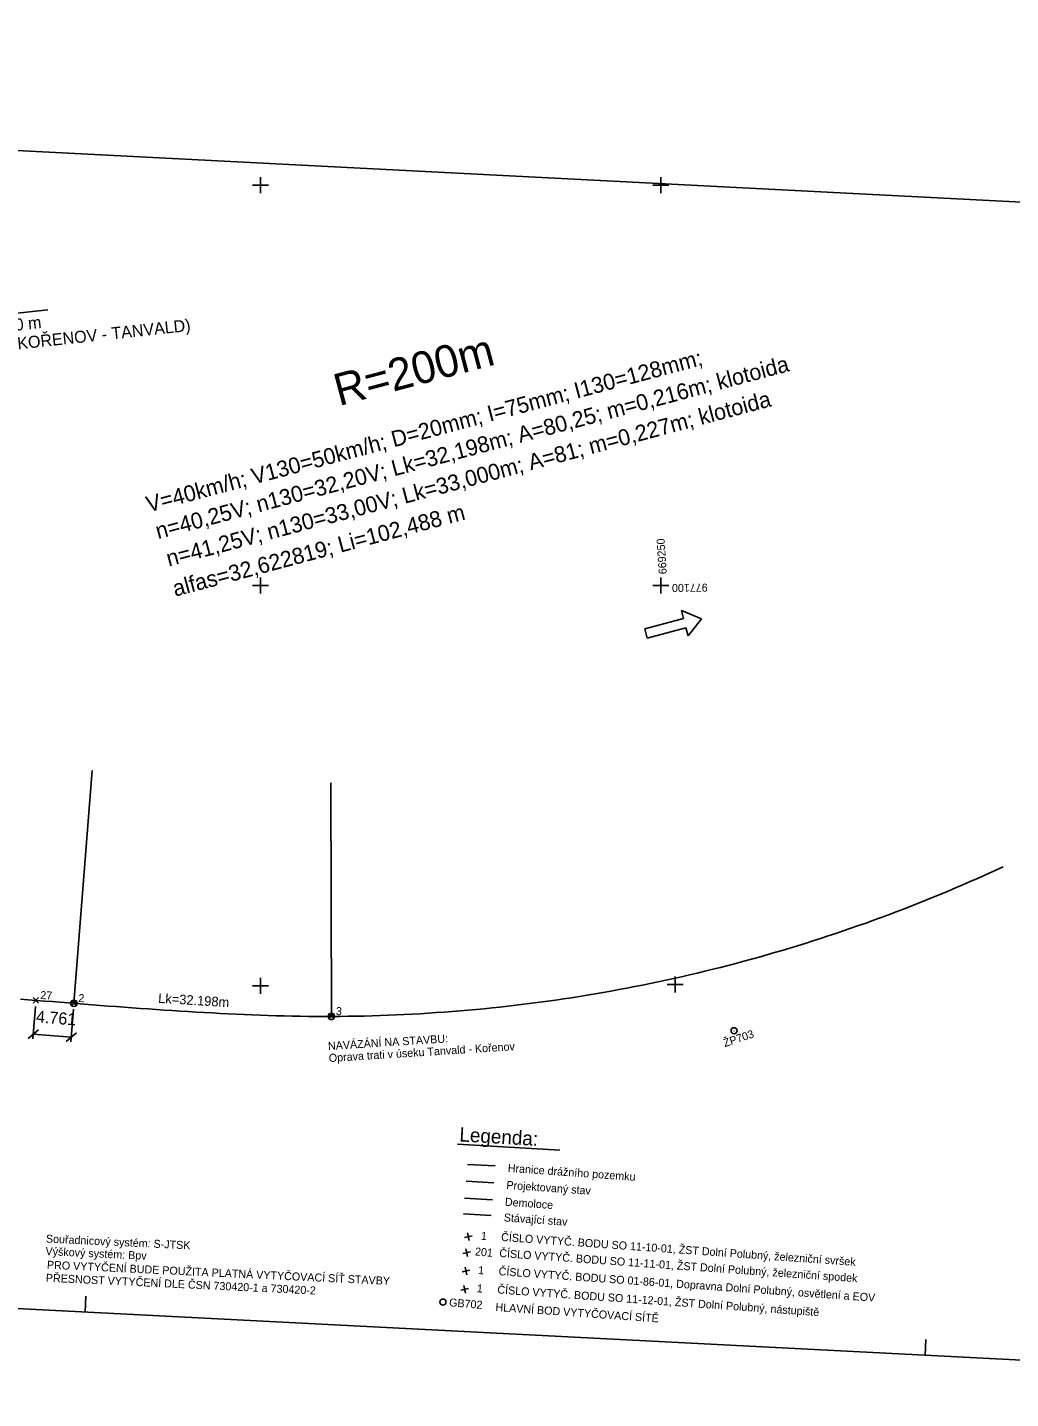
# Model space of a CAD drawing. Extents: x -669661 to -669105, y -977202 to -977030.
# Drawn here: x -669329.1 to -669206.3, y -977201.6 to -977030.3 of the extents above; entities that cross this region are included whole.
import ezdxf

# ---------------------------------------------------------------- set-up
doc = ezdxf.new("R2010")
doc.units = 0
for name, color, linetype in [('000_rozpiska', 7, 'Continuous'), ('_osa popis', 7, 'Continuous'), ('_sklonovníky', 7, 'Continuous'), ('Katastr_HRANICE DRÁHY', 7, 'Continuous'), ('KOL_lomy sklonů', 7, 'Continuous'), ('legenda', 7, 'Continuous'), ('legenda barvy', 7, 'Continuous'), ('legenda_text', 7, 'Continuous'), ('OST_smery', 7, 'Continuous'), ('POP_koleje_hlavní', 7, 'Continuous'), ('POP_koleje_oblouky', 7, 'Continuous'), ('POP_koleje_popis směrové hlavní body a parametry oblouků', 7, 'Continuous'), ('POP_kóty', 7, 'Continuous'), ('POP_sovisející_stavba', 7, 'Continuous'), ('PROGI_rozpiska', 7, 'Continuous'), ('SO 01-20-01_Demolice', 7, 'Continuous'), ('SO 01-86-01_vytyč_body', 7, 'Continuous'), ('SO 11-10-01_vytyč_body', 7, 'Continuous'), ('SO 11-11-01_vytyč_body', 7, 'Continuous'), ('SO 11-12-01_vytyč_body', 7, 'Continuous'), ('Stávající stav', 7, 'Continuous'), ('Vrstva 63', 7, 'Continuous'), ('čtvercová síť', 7, 'Continuous'), ('ŽBP', 7, 'Continuous')]:
    doc.layers.add(name, color=color, linetype=linetype)

# ---------------------------------------------------------------- blocks, each defined once
blk = doc.blocks.new('_Oblique')
blk.add_line((-0.5, -0.5), (0.5, 0.5))
blk = doc.blocks.new('POINT_DISPLAY')
for p, q in [((-0.35, -0.35), (0.35, 0.35)), ((-0.35, 0.35), (0.35, -0.35))]:
    blk.add_line(p, q)

msp = doc.modelspace()

# ---------------------------------------------------------------- linework, layer by layer
at = {"layer": '000_rozpiska'}
for p, q in [((-669321.79, -977188.79), (-669321.89, -977190.79)), ((-669216.93, -977194.19), (-669217.03, -977196.18))]:
    msp.add_line(p, q, dxfattribs=at)
at = {"layer": 'Defpoints'}
for p, q in [((-669629.05, -977030.28), (-669104.74, -977057.27)), ((-669629.05, -977030.28), (-669104.74, -977057.27)), ((-669636.48, -977174.59), (-669112.17, -977201.58)), ((-669636.48, -977174.59), (-669112.17, -977201.58))]:
    msp.add_line(p, q, dxfattribs=at)
at = {"layer": 'Katastr_HRANICE DRÁHY'}
msp.add_line((-669270.69, -977172.52), (-669274.16, -977172.32), dxfattribs=at)
at = {"layer": 'KOL_lomy sklonů'}
msp.add_lwpolyline([(-669341.46, -977067.18), (-669326.55, -977065.58)], dxfattribs=at)
at = {"layer": 'legenda barvy'}
msp.add_line((-669270.85, -977174.64), (-669274.33, -977174.43), dxfattribs=at)
at = {"layer": 'legenda_text'}
msp.add_line((-669275.39, -977169.8), (-669262.61, -977170.55), dxfattribs=at)
at = {"layer": 'OST_smery'}
for p, q in [((-669247.45, -977103.11), (-669244.94, -977104.16)), ((-669247.45, -977103.11), (-669247.18, -977104.13)), ((-669252.02, -977105.4), (-669247.18, -977104.13)), ((-669246.61, -977106.31), (-669244.94, -977104.16)), ((-669252.02, -977105.4), (-669251.71, -977106.57)), ((-669251.71, -977106.57), (-669246.88, -977105.29)), ((-669246.88, -977105.29), (-669246.61, -977106.31))]:
    msp.add_line(p, q, dxfattribs=at)
at = {"layer": 'POP_koleje_hlavní'}
for centre in [(-669323.3, -977152.2), (-669291.15, -977153.84)]:
    msp.add_circle(centre, 0.4, dxfattribs=at)
at = {"layer": 'POP_koleje_popis směrové hlavní body a parametry oblouků'}
for points in [[(-669321.01, -977123.12), (-669323.3, -977152.2)], [(-669291.22, -977124.66), (-669291.15, -977153.84)]]:
    msp.add_lwpolyline(points, dxfattribs=at)
at = {"layer": 'POP_kóty'}
for p, q in [((-669328.1, -977152.58), (-669328.42, -977156.66)), ((-669323.36, -977152.95), (-669323.68, -977157.03)), ((-669328.38, -977156.06), (-669323.63, -977156.43))]:
    msp.add_line(p, q, dxfattribs=at)
at = {"layer": 'POP_sovisející_stavba'}
for points in [[(-669290.76, -977153.84), (-669290.05, -977153.83), (-669289.05, -977153.82), (-669288.05, -977153.81), (-669287.05, -977153.79), (-669286.05, -977153.76), (-669285.06, -977153.73), (-669284.06, -977153.69), (-669283.06, -977153.65), (-669282.06, -977153.61), (-669281.06, -977153.56), (-669280.06, -977153.5), (-669279.06, -977153.44), (-669278.06, -977153.37), (-669277.07, -977153.3), (-669276.07, -977153.23), (-669275.07, -977153.15), (-669274.08, -977153.06), (-669273.08, -977152.97), (-669272.09, -977152.88), (-669271.09, -977152.77), (-669270.1, -977152.67), (-669269.1, -977152.56), (-669268.11, -977152.44), (-669267.12, -977152.32), (-669266.12, -977152.2), (-669265.13, -977152.07), (-669264.14, -977151.93), (-669263.15, -977151.79), (-669262.16, -977151.65), (-669261.17, -977151.5), (-669260.19, -977151.34), (-669259.2, -977151.18), (-669258.21, -977151.01), (-669257.23, -977150.84), (-669256.24, -977150.67), (-669255.26, -977150.49), (-669254.28, -977150.31), (-669253.29, -977150.12), (-669252.31, -977149.92), (-669251.33, -977149.72), (-669250.35, -977149.52), (-669249.38, -977149.31), (-669248.4, -977149.09), (-669247.42, -977148.88), (-669246.45, -977148.65), (-669245.48, -977148.42), (-669244.5, -977148.19), (-669243.53, -977147.95), (-669242.56, -977147.71), (-669241.59, -977147.46), (-669240.63, -977147.21), (-669239.66, -977146.95), (-669238.7, -977146.69), (-669237.73, -977146.42), (-669236.77, -977146.15), (-669235.81, -977145.87), (-669234.85, -977145.59), (-669233.89, -977145.3), (-669232.93, -977145.01), (-669231.98, -977144.71), (-669231.03, -977144.41), (-669230.07, -977144.1), (-669229.12, -977143.79), (-669228.17, -977143.48), (-669227.23, -977143.16), (-669226.28, -977142.83), (-669225.34, -977142.5), (-669224.39, -977142.17), (-669223.45, -977141.83), (-669222.51, -977141.49), (-669221.58, -977141.14), (-669220.64, -977140.79), (-669219.71, -977140.43), (-669218.78, -977140.07), (-669217.85, -977139.7), (-669216.92, -977139.33), (-669215.99, -977138.95), (-669215.07, -977138.57), (-669214.14, -977138.18), (-669213.22, -977137.79), (-669212.3, -977137.4), (-669211.39, -977137), (-669210.47, -977136.6), (-669209.56, -977136.19), (-669208.65, -977135.78), (-669207.28, -977135.15)], [(-669329.98, -977151.68), (-669328.99, -977151.76), (-669327.99, -977151.84), (-669326.99, -977151.92), (-669325.99, -977151.99), (-669325, -977152.07), (-669324, -977152.15), (-669323.3, -977152.2), (-669323, -977152.23), (-669322.01, -977152.3), (-669321.03, -977152.38), (-669321.01, -977152.38), (-669320.01, -977152.46), (-669319.02, -977152.54), (-669318.02, -977152.61), (-669317.02, -977152.69), (-669316.02, -977152.76), (-669315.03, -977152.83), (-669314.03, -977152.9), (-669313.03, -977152.97), (-669312.03, -977153.04), (-669311.04, -977153.11), (-669310.04, -977153.18), (-669309.04, -977153.24), (-669308.04, -977153.3), (-669307.04, -977153.36), (-669306.05, -977153.41), (-669305.05, -977153.47), (-669304.05, -977153.52), (-669303.05, -977153.56), (-669302.05, -977153.61), (-669301.05, -977153.65), (-669300.05, -977153.69), (-669299.05, -977153.72), (-669298.05, -977153.75), (-669297.05, -977153.77), (-669296.05, -977153.8), (-669295.05, -977153.81), (-669294.05, -977153.83), (-669293.05, -977153.84), (-669292.05, -977153.84), (-669291.15, -977153.84), (-669291.05, -977153.84), (-669290.76, -977153.84)]]:
    msp.add_lwpolyline(points, dxfattribs=at)
at = {"layer": 'PROGI_rozpiska'}
msp.add_circle((-669277.22, -977189.53), 0.375, dxfattribs=at)
at = {"layer": 'SO 01-20-01_Demolice'}
msp.add_line((-669271.05, -977176.74), (-669274.52, -977176.54), dxfattribs=at)
at = {"layer": 'Stávající stav'}
msp.add_line((-669271.18, -977178.7), (-669274.65, -977178.49), dxfattribs=at)
at = {"layer": 'čtvercová síť'}
for p, q in [((-669299, -977050), (-669301, -977050)), ((-669299, -977050), (-669301, -977050)), ((-669300, -977049), (-669300, -977051)), ((-669249, -977050), (-669251, -977050)), ((-669249, -977050), (-669251, -977050)), ((-669250, -977049), (-669250, -977051)), ((-669300, -977099), (-669300, -977101)), ((-669250, -977099), (-669250, -977101)), ((-669299, -977100), (-669301, -977100)), ((-669299, -977100), (-669301, -977100)), ((-669249, -977100), (-669251, -977100)), ((-669249, -977100), (-669251, -977100)), ((-669300, -977149), (-669300, -977151)), ((-669248.24, -977148.85), (-669248.24, -977150.85)), ((-669299, -977150), (-669301, -977150)), ((-669299, -977150), (-669301, -977150)), ((-669247.24, -977149.85), (-669249.24, -977149.85)), ((-669247.24, -977149.85), (-669249.24, -977149.85))]:
    msp.add_line(p, q, dxfattribs=at)
at = {"layer": 'ŽBP'}
msp.add_line((-669240.85, -977155.63), (-669240.9, -977155.63), dxfattribs=at)
msp.add_circle((-669240.87, -977155.63), 0.378, dxfattribs=at)

# ---------------------------------------------------------------- block references
at = {"layer": 'POP_kóty', "xscale": 1.2000000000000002, "yscale": 1.2000000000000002}
for p, rotation in [((-669328.38, -977156.06), 175.54902811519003), ((-669323.63, -977156.43), -4.450971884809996)]:
    msp.add_blockref('_Oblique', p, dxfattribs=dict(at, rotation=rotation))
at = {"layer": 'SO 01-86-01_vytyč_body', "rotation": 57.105270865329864}
msp.add_blockref('POINT_DISPLAY', (-669274.34, -977185.64), dxfattribs=at)
at = {"layer": 'SO 11-10-01_vytyč_body'}
for p in [(-669328.05, -977151.83), (-669323.3, -977152.2), (-669291.15, -977153.84)]:
    msp.add_blockref('POINT_DISPLAY', p, dxfattribs=at)
at = {"layer": 'SO 11-10-01_vytyč_body', "rotation": 57.105270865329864}
msp.add_blockref('POINT_DISPLAY', (-669274.04, -977181.35), dxfattribs=at)
at = {"layer": 'SO 11-11-01_vytyč_body', "rotation": 57.105270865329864}
msp.add_blockref('POINT_DISPLAY', (-669274.27, -977183.37), dxfattribs=at)
at = {"layer": 'SO 11-12-01_vytyč_body', "rotation": 57.105270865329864}
msp.add_blockref('POINT_DISPLAY', (-669274.51, -977187.92), dxfattribs=at)

# ---------------------------------------------------------------- texts
at = {"layer": '000_rozpiska'}
for s, p in [('Souřadnicový systém: S-JTSK', (-669326.81, -977182.09)), ('Výškový systém: Bpv', (-669326.86, -977183.65)), ('PRO VYTYČENÍ BUDE POUŽITA PLATNÁ VYTYČOVACÍ SÍŤ STAVBY', (-669326.68, -977185.35)), ('PŘESNOST VYTYČENÍ DLE ČSN 730420-1 a 730420-2', (-669326.82, -977186.98))]:
    msp.add_text(s, height=1, rotation=357.2783, dxfattribs=at).set_placement(p)
at = {"layer": '_osa popis'}
for s, height, p in [('R=200m', 4, (-669290.2, -977077.6)), ('V=40km/h; V130=50km/h; D=20mm; I=75mm; I130=128mm;', 2, (-669313.97, -977090.88)), ('n=41,25V; n130=33,00V; Lk=33,000m; A=81; m=0,227m; klotoida', 2, (-669311.46, -977097.64))]:
    msp.add_text(s, height=height, rotation=14.9006, dxfattribs=at).set_placement(p)
at = {"layer": '_sklonovníky'}
for s, p in [('NAVÁZÁNÍ NA STAVBU:', (-669291.54, -977158.04)), ('Oprava trati v úseku Tanvald - Kořenov', (-669291.44, -977159.54))]:
    msp.add_text(s, height=1, rotation=3.643, dxfattribs=at).set_placement(p)
at = {"layer": 'KOL_lomy sklonů'}
for s, p in [('dl.152,500 m', (-669338.82, -977069.07)), ('SKLON (KOŘENOV - TANVALD)', (-669338.26, -977071.38))]:
    msp.add_text(s, height=1.5, rotation=6.1516, dxfattribs=at).set_placement(p)
at = {"layer": 'legenda'}
for s, p in [('Hranice drážního pozemku', (-669269.15, -977173.26)), ('Projektovaný stav', (-669269.32, -977175.38)), ('Demoloce', (-669269.51, -977177.48)), ('Stávající stav', (-669269.64, -977179.44)), ('ČÍSLO VYTYČ. BODU SO 11-10-01, ŽST Dolní Polubný, železniční svršek', (-669269.98, -977181.88)), ('ČÍSLO VYTYČ. BODU SO 11-11-01, ŽST Dolní Polubný, železniční spodek', (-669270.21, -977183.89)), ('ČÍSLO VYTYČ. BODU SO 01-86-01, Dopravna Dolní Polubný, osvětlení a EOV', (-669270.29, -977186.16)), ('ČÍSLO VYTYČ. BODU SO 11-12-01, ŽST Dolní Polubný, nástupiště', (-669270.45, -977188.45)), ('HLAVNÍ BOD VYTYČOVACÍ SÍTĚ', (-669270.69, -977190.63))]:
    msp.add_text(s, height=1, rotation=355.9604, dxfattribs=at).set_placement(p)
at = {"layer": 'legenda_text'}
msp.add_text('Legenda:', height=1.762, rotation=356.6577, dxfattribs=at).set_placement((-669275.2, -977169.45))
at = {"layer": 'POP_koleje_oblouky'}
for s, height, rotation, p in [('n=40,25V; n130=32,20V; Lk=32,198m; A=80,25; m=0,216m; klotoida', 2, 14.9006, (-669312.8, -977094.21)), ('alfas=32,622819; Li=102,488 m', 2, 14.9006, (-669310.65, -977101.4)), ('Lk=32.198m', 1.2, 356.4751, (-669312.8, -977152.14))]:
    msp.add_text(s, height=height, rotation=rotation, dxfattribs=at).set_placement(p)
at = {"layer": 'POP_kóty'}
msp.add_text('4.761', height=1.5, rotation=355.549, dxfattribs=at).set_placement((-669328.07, -977154.58))
at = {"layer": 'SO 01-86-01_vytyč_body'}
msp.add_text('1', height=1, rotation=355.0289, dxfattribs=at).set_placement((-669272.86, -977186.01))
at = {"layer": 'SO 11-10-01_vytyč_body'}
for s, rotation, p in [('27', 356.8465, (-669327.51, -977151.66)), ('2', 356.8465, (-669322.76, -977152.03)), ('3', 356.8465, (-669290.61, -977153.66)), ('1', 355.0289, (-669272.51, -977181.73))]:
    msp.add_text(s, height=1, rotation=rotation, dxfattribs=at).set_placement(p)
at = {"layer": 'SO 11-11-01_vytyč_body'}
msp.add_text('201', height=1, rotation=355.0289, dxfattribs=at).set_placement((-669273.25, -977183.69))
at = {"layer": 'SO 11-12-01_vytyč_body'}
msp.add_text('1', height=1, rotation=355.0289, dxfattribs=at).set_placement((-669273.02, -977188.29))
at = {"layer": 'Vrstva 63'}
msp.add_text('GB702', height=1, rotation=355.3756, dxfattribs=at).set_placement((-669276.48, -977190.05))
at = {"layer": 'čtvercová síť'}
for s, rotation, p in [('669250', 93.6158, (-669249.27, -977098.56)), ('977100', 180.6138, (-669244.17, -977099.77))]:
    msp.add_text(s, height=1, rotation=rotation, dxfattribs=at).set_placement(p)
at = {"layer": 'ŽBP'}
msp.add_text('ŽP703', height=1, rotation=18.4882, dxfattribs=at).set_placement((-669242.02, -977157.68))

doc.saveas('drawing.dxf')
